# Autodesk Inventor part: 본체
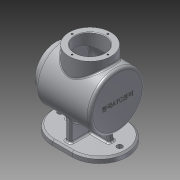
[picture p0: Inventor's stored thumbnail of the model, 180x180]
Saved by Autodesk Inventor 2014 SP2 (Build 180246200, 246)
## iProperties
Created: 2016-04
Part Number: 본체
Material: 알루미늄 6061
Document SubType Name: Modeling
Designer: 201-25
Density: 2.71 g/cm^3
Appearance: 알루미늄 - 평지
Mass: 904.019 g
Surface Area: 1219.31 cm^2
Volume: 333.586 cm^3
Author: 201-25
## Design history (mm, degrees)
sketch "스케치1"
  geometry: L1 (-67.5, 50)-(67.5, 50); L2 (67.5, 50)-(67.5, -50); L3 (67.5, -50)-(-67.5, -50); L4 (-67.5, -50)-(-67.5, 50); 3 further points
  constraints: 8 end point, 2 midpoint, 2 parallel, 1 horizontal, 1 horizontal alignment, 1 perpendicular, 1 vertical alignment
  dimensions: "d5" = 135 distance of L2.end L3.end; "d6" = 100 distance of L1.end L2.end
extrude "돌출1" new body sketch "스케치1" distance "d7" = 10; taper "d8" = 0 deg
fillet "모깎기1" dims "d9" = 50
sketch "스케치2"
  geometry: L1 (50, 0)-(-50, 0) reference; C1 r 50 at (0, 79); 1 further point
  constraints: 1 centre point
  dimensions: "d10" = 100 diameter of C1; "d11" = 79 distance from line of L1 C1.centre
extrude "돌출2" join sketch "스케치2" stored distance "d12" = 100; taper "d13" = 0 deg
sketch "스케치3"
  geometry: C1 r 38 at (0, 0); 1 further point
  constraints: 1 centre point
  dimensions: "d14" = 76 diameter of C1
extrude "돌출3" join sketch "스케치3" distance "d15" = 12; taper "d16" = 0 deg
node "작업 평면1"
sketch "스케치4"
  geometry: C1 r 38 at (0, 0); 1 further point
  constraints: 1 centre point
  dimensions: "d18" = 76 diameter of C1
extrude "돌출4" join sketch "스케치4" stored distance "d19" = 12; taper "d20" = 0 deg
sketch "스케치5"
  geometry: L1 (-5, 40)-(5, 40); L2 (5, 40)-(5, -40); L3 (5, -40)-(-5, -40); L4 (-5, -40)-(-5, 40); C1 r 38 at (0, 0) reference; 2 further points
  constraints: 8 end point, 2 midpoint, 2 parallel, 1 horizontal, 1 horizontal alignment, 1 perpendicular, 1 vertical alignment
  dimensions: "d27" = 10 distance of L2.end L3.end; "d28" = 80 distance of L1.end L2.end
extrude "돌출5" join sketch "스케치5" stored distance "d29" = 12; taper "d30" = 0 deg
sketch "스케치7"
  geometry: C1 r 27 at (0, 0); 1 further point
  constraints: 1 centre point
  dimensions: "d35" = 54 diameter of C1
extrude "돌출7" cut sketch "스케치7" distance "d36" = 15; taper "d37" = 0 deg
sketch "스케치10"
  geometry: C1 r 27 at (0, 0) reference; 2 further points
  dimensions: "d38" = 32.5 distance of C1.centre point (32.5, 0)
hole "구멍1" sketch "스케치10" at (32.5, 0) diameter "d39" = 3.242; stored, may be unused: countersink angle "d43" = 90 deg, drill point angle "d45" = 118 deg; dims "d40" = 8, "d41" = 19.05, "d42" = 4.775, "d44" = 10
chamfer "모따기1" distance "d49" = 1; stored, may be unused: second distance "d50" = 2, angle "d51" = 45 deg
fillet "모깎기2" dims "d52" = 5
fillet "모깎기3" dims "d53" = 3
sketch "스케치11"
  geometry: C1 r 38 at (0, 0) reference; 1 further point
  dimensions: "d54" = 32.5 distance of point (32.5, 0) C1.centre
hole "구멍2" sketch "스케치11" at (32.5, 0) diameter "d55" = 3.242; stored, may be unused: countersink angle "d59" = 90 deg, drill point angle "d61" = 118 deg; dims "d56" = 8, "d57" = 19.05, "d58" = 4.775, "d60" = 10
chamfer "모따기2" distance "d65" = 3; stored, may be unused: second distance "d66" = 2, angle "d67" = 45 deg
fillet "모깎기4" dims "d68" = 3
fillet "모깎기5" dims "d69" = 3
sketch "스케치12"
  geometry: C1 r 47 at (0, 0); 1 further point
  constraints: 1 centre point
  dimensions: "d70" = 94 diameter of C1
extrude "돌출8" cut sketch "스케치12" distance "d71" = 94; taper "d72" = 0 deg
sketch "스케치13"
  geometry: C1 r 27 at (0, 0)
  constraints: 1 centre point
  dimensions: "d73" = 54 diameter of C1
extrude "돌출9" cut sketch "스케치13" stored distance "d74" = 90; taper "d75" = 0 deg
chamfer "모따기3" distance "d76" = 1; stored, may be unused: second distance "d77" = 2, angle "d78" = 45 deg
sketch "스케치15"
  geometry: L1 (-4.203, -29.035)-(-4.203, 29.035); L2 (-4.203, 29.035)-(4.203, 29.035); L3 (4.203, 29.035)-(4.203, -29.035); L4 (4.203, -29.035)-(-4.203, -29.035); C1 r 50 at (0, 0) reference; 3 further points
  constraints: 2 midpoint, 1 horizontal alignment, 1 vertical alignment, 2 other
feature "엠보싱1" sketch "스케치15" dims "d5" = 135, "d6" = 100, "d79" = 0.5, "d80" = 0
sketch "스케치16"
  geometry: C1 r 5 at (-54, 0); C2 r 5 at (54, 0); 1 further point
  constraints: 2 centre point
  dimensions: "d87" = 10 diameter of C1; "d88" = 10 diameter of C2; "d89" = 54 distance of point (0, 0) C1.centre; "d90" = 54 distance of point (0, 0) C2.centre
extrude "돌출10" cut sketch "스케치16" stored distance "d85" = 90; taper "d86" = 0 deg
fillet "모깎기6" dims "d91" = 2
fillet "모깎기7" dims "d92" = 5
sketch "스케치17"
  geometry: L1 (45, 29)-(-45, 29) reference; L2 (17.5, 10)-(-17.5, 10) reference; L3 (-64.5, 10)-(-17.5, 10) reference; L4 (-36.071, 32.036)-(-40, 9.756); 2 further points
  constraints: 2 end point
  dimensions: "d93" = 100 deg angle of L3 L4; "d94" = 40 horizontal distance of L4.end point (0, 0)
feature "리브1" sketch "스케치17" dims "d95" = 10, "d96" = 10, "d97" = 0, "d98" = 0, "d99" = 1, "d100" = 1
fillet "모깎기8" dims "d101" = 3
fillet "모깎기9" dims "d102" = 3
node "솔리드1"
pattern_circular "원형 패턴1" dims angle "d47" = 360 deg
pattern_circular "원형 패턴2" dims angle "d63" = 360 deg
mirror "대칭1"
other parameters: "d17" = 144
